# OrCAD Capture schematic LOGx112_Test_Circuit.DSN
size A; title: LOGx112, Precision LOGARITHMIC AND LOG RATIO AMPLIFIER; rev: 1.1; note: Datasheet: SBOS246D EVM: N/A
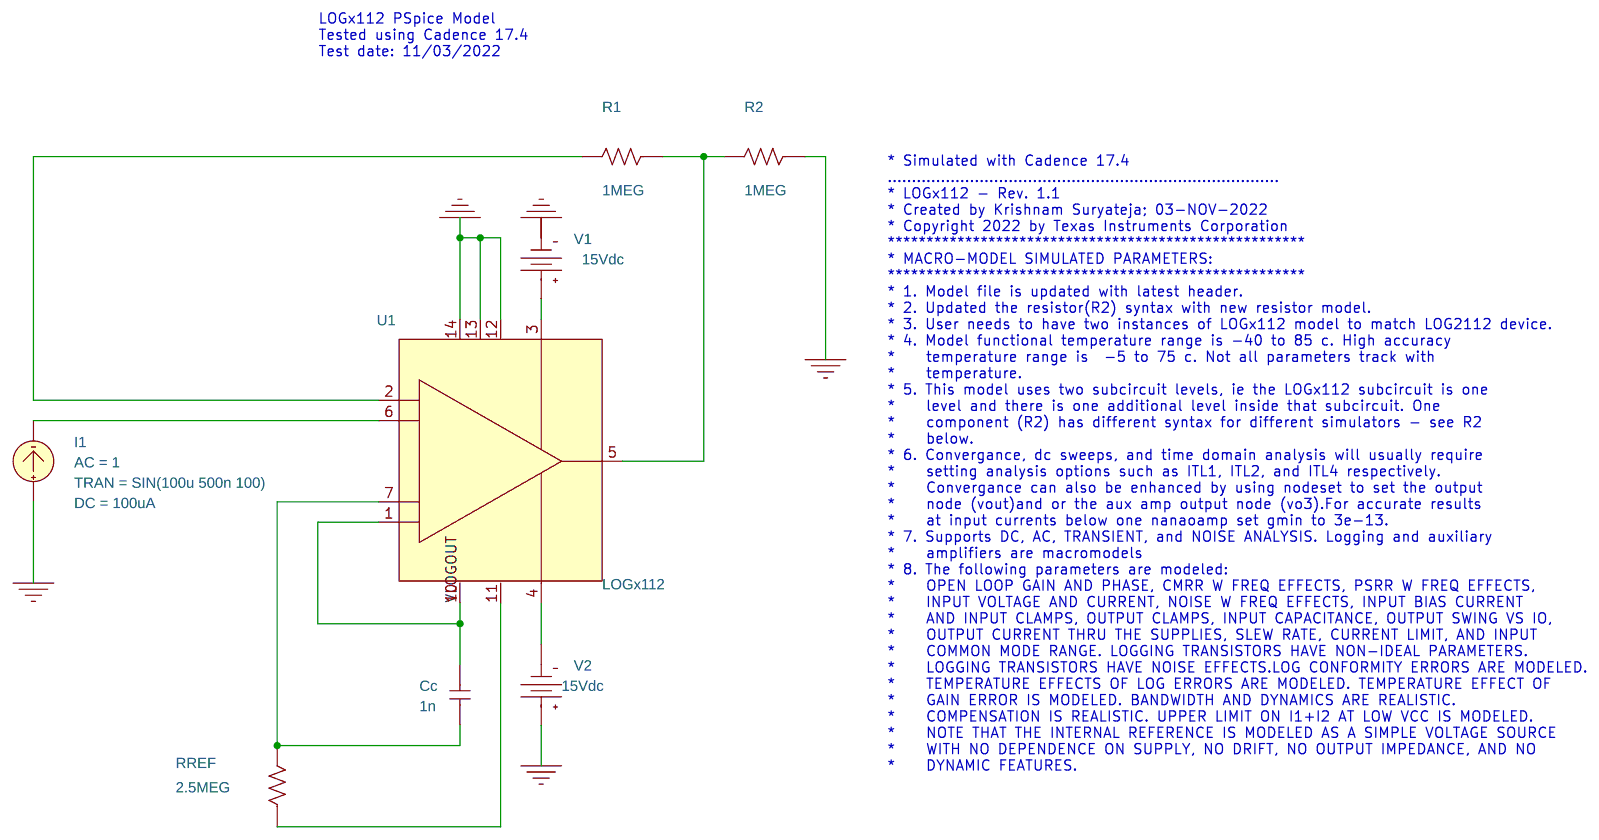
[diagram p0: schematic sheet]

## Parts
Cc  1n  [RAD/CK05]
I1  ISRC
R1  1MEG  [AXRC05]
R2  1MEG  [AXRC05]
RREF  2.5MEG  [AXRC05]
U1  LOGx112
V1  VDC
V2  VDC

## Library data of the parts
Cc = C
I1 = ISRC: AC: 1; DC: 100uA; TRAN: SIN(100u 500n 100)
R1 R2 RREF = R
U1 = LOGx112
V1 V2 = VDC: DC: 15Vdc

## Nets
0: I1.1(+) R2.1 U1.12(REFGND) U1.13(VCM) U1.14(GND) V1.1(-) V2.0(+)
VLOGOUT: Cc.1 U1.1(+) U1.10(VLOG)
N14296378: I1.2(-) U1.6(I1)
N14296728: Cc.2 RREF.2 U1.7(I2)
N14296794: R1.2 U1.2(-)
N14296975: R1.1 R2.2 U1.5(VO3)
N14297312: U1.4(V-) V2.1(-)
N14297449: U1.3(V+) V1.0(+)
N14300314: RREF.1 U1.11(VREF)

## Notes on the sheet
- LOGx112 PSpice Model
  Tested using Cadence 17.4
  Test date: 11/03/2022
- * Simulated with Cadence 17.4
  .................................................................................
  * LOGx112 - Rev. 1.1
  * Created by Krishnam Suryateja; 03-NOV-2022
  * Copyright 2022 by Texas Instruments Corporation
  ******************************************************
  * MACRO-MODEL SIMULATED PARAMETERS:
  ******************************************************
  * 1. Model file is updated with latest header.
  * 2. Updated the resistor(R2) syntax with new resistor model.
  * 3. User needs to have two instances of LOGx112 model to match LOG2112 device.
  * 4. Model functional temperature range is -40 to 85 c. High accuracy
  *    temperature range is  -5 to 75 c. Not all parameters track with
  *    temperature.
  * 5. This model uses two subcircuit levels, ie the LOGx112 subcircuit is one
  *    level and there is one additional level inside that subcircuit. One
  *    component (R2) has different syntax for different simulators - see R2
  *    below.
  * 6. Convergance, dc sweeps, and time domain analysis will usually require
  *    setting analysis options such as ITL1, ITL2, and ITL4 respectively.
  *    Convergance can also be enhanced by using nodeset to set the output
  *    node (vout)and or the aux amp output node (vo3).For accurate results
  *    at input currents below one nanaoamp set gmin to 3e-13.
  * 7. Supports DC, AC, TRANSIENT, and NOISE ANALYSIS. Logging and auxiliary
  *    amplifiers are macromodels
  * 8. The following parameters are modeled:
  *    OPEN LOOP GAIN AND PHASE, CMRR W FREQ EFFECTS, PSRR W FREQ EFFECTS,
  *    INPUT VOLTAGE AND CURRENT, NOISE W FREQ EFFECTS, INPUT BIAS CURRENT
  *    AND INPUT CLAMPS, OUTPUT CLAMPS, INPUT CAPACITANCE, OUTPUT SWING VS IO,
  *    OUTPUT CURRENT THRU THE SUPPLIES, SLEW RATE, CURRENT LIMIT, AND INPUT
  *    COMMON MODE RANGE. LOGGING TRANSISTORS HAVE NON-IDEAL PARAMETERS.
  *    LOGGING TRANSISTORS HAVE NOISE EFFECTS.LOG CONFORMITY ERRORS ARE MODELED.
  *    TEMPERATURE EFFECTS OF LOG ERRORS ARE MODELED. TEMPERATURE EFFECT OF
  *    GAIN ERROR IS MODELED. BANDWIDTH AND DYNAMICS ARE REALISTIC.
  *    COMPENSATION IS REALISTIC. UPPER LIMIT ON I1+I2 AT LOW VCC IS MODELED.
  *    NOTE THAT THE INTERNAL REFERENCE IS MODELED AS A SIMPLE VOLTAGE SOURCE
  *    WITH NO DEPENDENCE ON SUPPLY, NO DRIFT, NO OUTPUT IMPEDANCE, AND NO
  *    DYNAMIC FEATURES.
